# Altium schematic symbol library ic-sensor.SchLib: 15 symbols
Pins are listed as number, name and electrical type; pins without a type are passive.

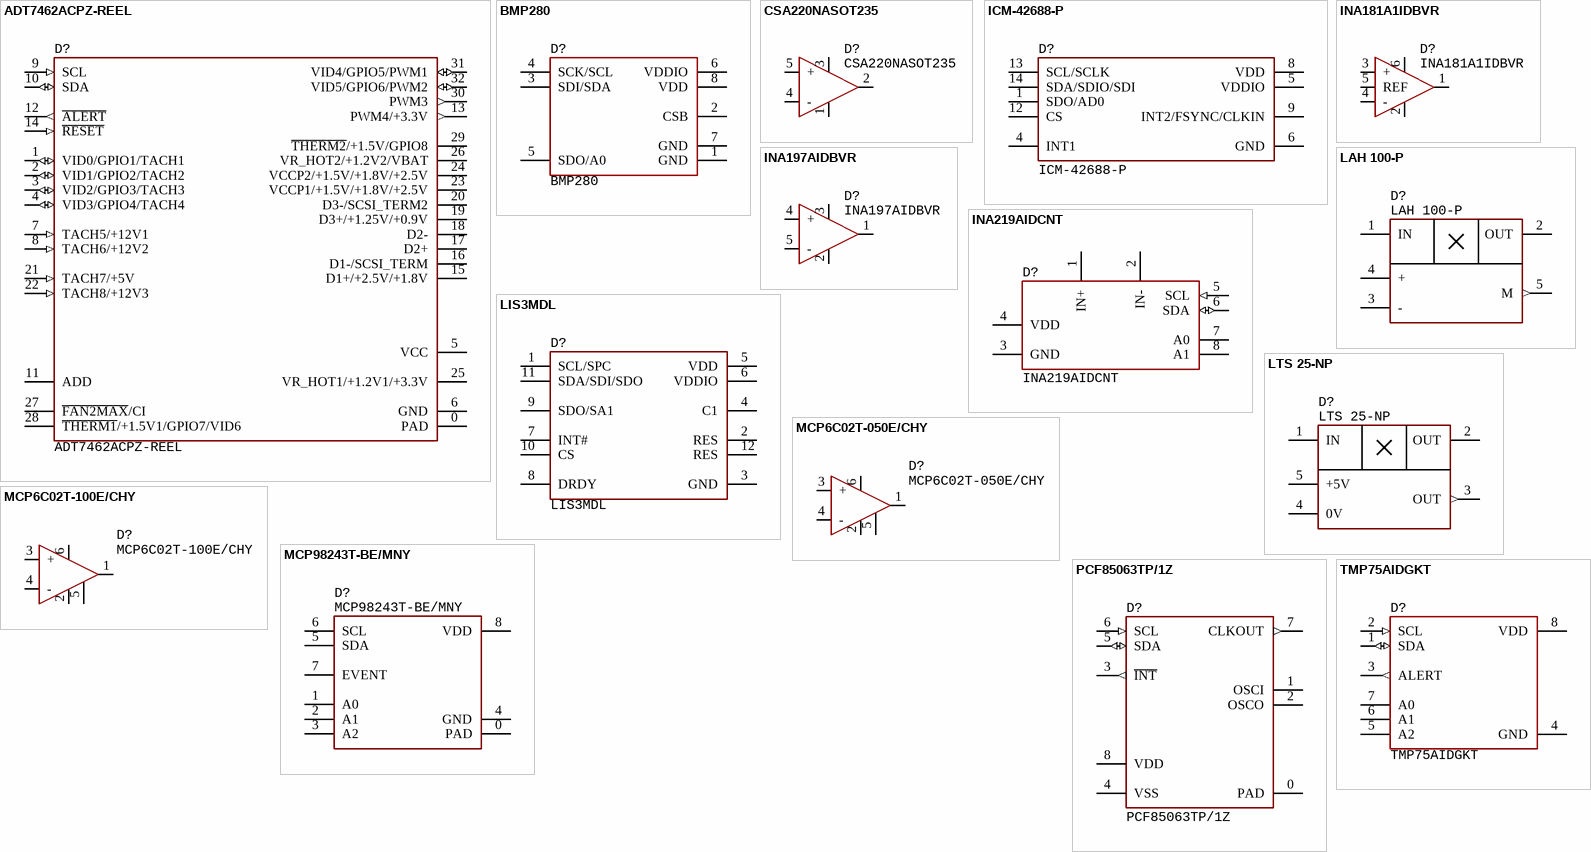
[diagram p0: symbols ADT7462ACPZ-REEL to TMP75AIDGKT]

## ADT7462ACPZ-REEL
designator D?
Fan Monitor, SMBus, LFCSP-32, supply 3...5.5V, -40...+125°C; Manufacturer: ON Semiconductor
footprint 32-QFN (5x5, pitch 0.5) (5x5 mm, pitch 0.5 mm, power pad)
pins: 0 PAD, 1 VID0/GPIO1/TACH1 (io), 2 VID1/GPIO2/TACH2 (io), 3 VID2/GPIO3/TACH3 (io), 4 VID3/GPIO4/TACH4 (io), 5 VCC, 6 GND, 7 TACH5/+12V1 (in), 8 TACH6/+12V2 (in), 9 SCL (in), 10 SDA (io), 11 ADD, 12 ~{ALERT} (out), 13 PWM4/+3.3V (out), 14 ~{RESET} (in), 15 D1+/+2.5V/+1.8V, 16 D1-/SCSI_TERM, 17 D2+, 18 D2-, 19 D3+/+1.25V/+0.9V, 20 D3-/SCSI_TERM2, 21 TACH7/+5V (in), 22 TACH8/+12V3 (in), 23 VCCP1/+1.5V/+1.8V/+2.5V, 24 VCCP2/+1.5V/+1.8V/+2.5V, 25 VR_HOT1/+1.2V1/+3.3V, 26 VR_HOT2/+1.2V2/VBAT, 27 ~{FAN2MAX}/CI, 28 ~{THERM1}/+1.5V1/GPIO7/VID6, 29 ~{THERM2}/+1.5V/GPIO8, 30 PWM3 (out), 31 VID4/GPIO5/PWM1 (io), 32 VID5/GPIO6/PWM2 (io)

## BMP280
designator D?
Pressure sensor, I2C/SPI, 300...1100 hPa, ±0.12 hPa, LGA-8, supply 1.71...3.6V, -40...+85°C; Manufacturer: Bosch
footprint 8-LGA (2.5x2, 0.65 mm)
pins: 1 GND, 2 CSB, 3 SDI/SDA, 4 SCK/SCL, 5 SDO/A0, 6 VDDIO, 7 GND, 8 VDD

## CSA220NASOT235
designator D?
Current monitor, 60 kHz, 50V/V, max 76V,  supply 2.7...5.5V, SOT23-5,  -40...+125°C; Manufacturer: Analogy Semi
footprint SOT23-5 (pitch 0.95 mm)
pins: 1 GND (power), 2 OUT (power), 3 VDD (power), 4 -, 5 +

## ICM-42688-P
designator D?
IMU, 6-axis, I2C/I3C/SPI, 20 bit, ±16g, LGA-8, supply 1.71...3.6V, -40...+85°C; Manufacturer: TDK
footprint 14-LGA (3x2.5, pitch 0.5 mm)
pins: 1 SDO/AD0, 4 INT1, 5 VDDIO, 6 GND, 8 VDD, 9 INT2/FSYNC/CLKIN, 12 CS, 13 SCL/SCLK, 14 SDA/SDIO/SDI

## INA181A1IDBVR
designator D?
Current monitor, 350 kHz, 20V/V, max 26V,  supply 2.7...5.5V, SOT23-6,  -40...+125°C; Manufacturer: Texas Instruments
footprint SOT23-6 (pitch 0.95 mm)
pins: 1 OUT (power), 2 GND (power), 3 +, 4 -, 5 REF, 6 VDD (power)

## INA197AIDBVR
designator D?
Current monitor, 500 kHz, 50V/V, max 80V,  supply 2.7...18V, SOT23-5,  -40...+125°C; Manufacturer: Texas Instruments
footprint SOT23-5 (pitch 0.95 mm)
pins: 1 OUT (power), 2 GND (power), 3 VDD (power), 4 +, 5 -

## INA219AIDCNT
designator D?
V/I monitor, 11b, ±1%, I2C/SMBus, supply 3...5.5V, SOT-23-8, -40...+125°C; Manufacturer: Texas Instruments
footprint SOT23-8 (pitch 0.95 mm)
pins: 1 IN+, 2 IN-, 3 GND, 4 VDD, 5 SCL (in), 6 SDA (io), 7 A0, 8 A1

## LAH 100-P
designator D?
Current sensors, 100A, 0...200 kHz, 0.5%, supply 15V, 500 ns, -40...+85°C; Manufacturer: LEM
footprint SENSOR: LAH 100-P
pins: 1 IN, 2 OUT, 3 -, 4 +, 5 M (out)

## LIS3MDL
designator D?
Magnetic sensor, I2C/SPI, 3-axis, LGA-12, 1.9...3.6V, -40...+85°C; Manufacturer: STMicroelectronics
footprint 12-LGA (2х2)
pins: 1 SCL/SPC, 2 RES, 3 GND, 4 C1, 5 VDD, 6 VDDIO, 7 INT#, 8 DRDY, 9 SDO/SA1, 10 CS, 11 SDA/SDI/SDO, 12 RES

## LTS 25-NP
designator D?
Current sensors, 25A, 0...200 kHz, 0.5%, supply 5V, 500 ns, -40...+85°C; Manufacturer: LEM
footprint SENSOR: LTS 25-NP
pins: 1 IN, 2 OUT, 3 OUT (out), 4 0V, 5 +5V

## MCP6C02T-050E/CHY
designator D?
Current monitor, 500 kHz, input -3...+65V, ±3%, gain 50V/V, supply 2...5.5V, SOT23-6, -40...+125°C; Manufacturer: Microchip
footprint SOT23-6 (pitch 0.95 mm)
pins: 1 OUT (power), 2 GND (power), 3 +, 4 -, 5 REF, 6 VDD (power)

## MCP6C02T-100E/CHY
designator D?
Current monitor, 1000 kHz, input -3...+65V, ±3%, gain 100V/V, supply 2...5.5V, SOT23-6, -40...+125°C; Manufacturer: Microchip
footprint SOT23-6 (pitch 0.95 mm)
pins: 1 OUT (power), 2 GND (power), 3 +, 4 -, 5 REF, 6 VDD (power)

## MCP98243T-BE/MNY
designator D?
Temp sensor, I2C/SMbus, ±1°C, DFN-8, supply 1.8...5.5V, -20...+125°C; Manufacturer: Microchip
footprint 8-DFN (2x3, 0.5 mm)
pins: 0 PAD, 1 A0, 2 A1, 3 A2, 4 GND, 5 SDA, 6 SCL, 7 EVENT, 8 VDD

## PCF85063TP/1Z
designator D?
RTC Clock, I2C, supply 0.9...5.5V, DFN-8, -40...+85°C; Manufacturer: NXP
footprint 8-DFN (2x3, 0.5 mm)
pins: 0 PAD, 1 OSCI, 2 OSCO, 3 ~{INT} (out), 4 VSS, 5 SDA (io), 6 SCL (in), 7 CLKOUT (out), 8 VDD

## TMP75AIDGKT
designator D?
Temp sensor, I2C/SMbus, 11b, ±2°C, MSOP-8, supply 2.7...5.5V, -5...+125°C; Manufacturer: Texas Instruments
footprint 8-MSOP (pitch 0.65 mm)
pins: 1 SDA (io), 2 SCL (in), 3 ALERT (out), 4 GND, 5 A2, 6 A1, 7 A0, 8 VDD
